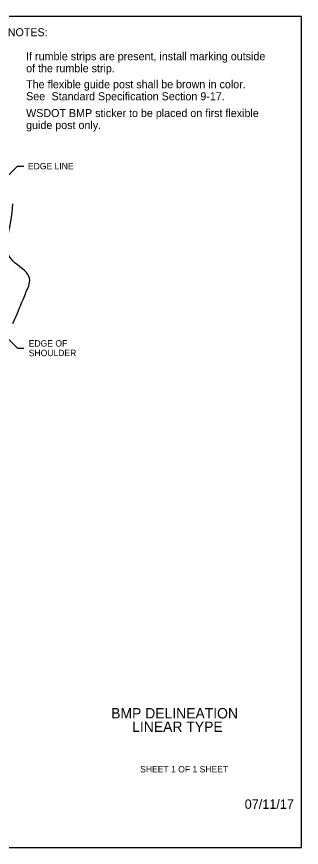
# Model space of a CAD drawing. Extents: x 99862 to 103151, y 100000 to 102076.
# Drawn here: x 102440 to 103151, y 100000 to 102076 of the extents above; entities that cross this region are included whole.
import ezdxf

# ---------------------------------------------------------------- set-up
doc = ezdxf.new("R2010")
doc.units = 0
for name, color, linetype in [('Level 1', 7, 'Continuous'), ('Level 15', 7, 'Continuous'), ('Level 20', 7, 'Continuous'), ('Level 60', 7, 'Continuous'), ('Level 62', 7, 'Continuous'), ('SH_DE_DetailLevel1', 7, 'Continuous'), ('SH_DE_DetailLevel9', 7, 'Continuous')]:
    doc.layers.add(name, color=color, linetype=linetype)

msp = doc.modelspace()

# ---------------------------------------------------------------- linework, layer by layer
at = {"layer": 'Level 1'}
msp.add_lwpolyline([(99862, 99999.5), (103151, 99999.5), (103151, 102075.5), (99862, 102075.5)], close=True, dxfattribs=at)
at = {"layer": 'Level 15'}
for p, q in [((102441.9, 101701.8), (102457.9, 101701.8)), ((102441.9, 101247), (102457.9, 101247))]:
    msp.add_line(p, q, dxfattribs=at)
at = {"layer": 'Level 60'}
msp.add_line((103151, 102075.5), (103151, 102075.5), dxfattribs=at)
at = {"layer": 'SH_DE_DetailLevel1'}
msp.add_open_spline([(102430.5, 101308.3), (102442.2, 101336.4), (102454, 101364.6), (102465.7, 101392.8), (102481.7, 101431.2), (102415, 101469.2), (102417.3, 101507.9), (102419.2, 101539), (102428, 101574.1), (102430.5, 101607.3)], degree=3, dxfattribs=at)
msp.add_open_spline([(102430.5, 101308.3), (102442.2, 101336.4), (102454, 101364.6), (102465.7, 101392.8), (102481.7, 101431.2), (102415, 101469.2), (102417.3, 101507.9), (102419.2, 101539), (102428, 101574.1), (102430.5, 101607.3)], degree=3, dxfattribs=at)
at = {"layer": 'SH_DE_DetailLevel9'}
for p, q in [((102380.6, 101640.5), (102441.9, 101701.8)), ((102380.6, 101308.3), (102441.9, 101247))]:
    msp.add_line(p, q, dxfattribs=at)

# ---------------------------------------------------------------- texts
at = {"layer": 'Level 15'}
msp.add_text('07/11/17', height=23.62, dxfattribs=at).set_placement((103009.4, 100095.8))
at = {"layer": 'Level 20'}
for s, height, p in [('NOTES:', 20, (102417.5, 102026.5)), ('If rumble strips are present, install marking outside ', 20, (102463.4, 101966.5)), ('of the rumble strip.', 20, (102463.4, 101936.5)), ('The flexible guide post shall be brown in color. ', 20, (102463.4, 101896.5)), ('See ', 20, (102463.4, 101866.5)), ('Standard Specification Section 9-17.', 20, (102526.9, 101866.5)), ('WSDOT BMP sticker to be placed on first flexible ', 20, (102463.4, 101824.5)), ('guide post only.', 20, (102463.4, 101794.5)), ('EDGE LINE', 16, (102467.9, 101693.8)), ('EDGE OF', 16, (102469.9, 101251)), ('SHOULDER', 16, (102469.9, 101227))]:
    msp.add_text(s, height=height, dxfattribs=at).set_placement(p)
at = {"layer": 'Level 62'}
for s, height, p in [('BMP DELINEATION', 26, (102675.8, 100321.7)), ('LINEAR TYPE', 26, (102728.3, 100287.9)), ('SHEET 1 OF 1 SHEET', 16, (102748.2, 100186.8))]:
    msp.add_text(s, height=height, dxfattribs=at).set_placement(p)

doc.saveas('drawing.dxf')
